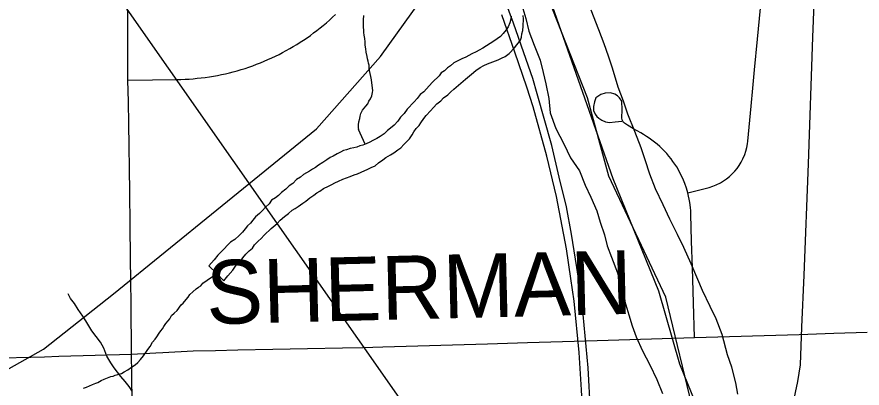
# Model space of a CAD drawing. Extents: x -6.1 to 38, y -7.7 to 22.
# Drawn here: x 4.199 to 4.953, y 17.079 to 17.41 of the extents above; entities that cross this region are included whole.
import ezdxf

# ---------------------------------------------------------------- set-up
doc = ezdxf.new("R2010")
doc.units = 0
for name, color, linetype in [('GM_X_Corporation', 7, 'Continuous'), ('GM_X_County_Road', 7, 'Continuous'), ('GM_X_Major_River', 7, 'Continuous'), ('GM_X_Minor_River', 7, 'Continuous'), ('GM_X_Rail_Line', 7, 'Continuous'), ('GM_X_State_Route', 7, 'Continuous'), ('GM_X_Township_Road', 7, 'Continuous'), ('GM_X_Township_Road_Text', 7, 'Continuous'), ('SH_Text', 7, 'Continuous')]:
    doc.layers.add(name, color=color, linetype=linetype)

msp = doc.modelspace()

# ---------------------------------------------------------------- linework, layer by layer
at = {"layer": 'GM_X_Corporation'}
for points in [[(4.78909, 16.45229), (4.83333, 16.6969), (4.8485, 16.80869), (4.84852, 16.86549), (4.82148, 16.98857), (4.80797, 17.05755), (4.79039, 17.10084), (4.77146, 17.16576), (4.7309, 17.26585), (4.64031, 17.52419)], [(4.78909, 16.45229), (4.83333, 16.6969), (4.8485, 16.80869), (4.84852, 16.86549), (4.82148, 16.98857), (4.80797, 17.05755), (4.79039, 17.10084), (4.77146, 17.16576), (4.7309, 17.26585), (4.64031, 17.52419)], [(4.79218, 16.42728), (4.80873, 16.54217), (4.81265, 16.56116), (4.82853, 16.688), (4.83806, 16.82118), (4.82856, 16.93533), (4.80321, 17.05583), (4.77785, 17.16048), (4.72713, 17.2683), (4.70812, 17.33806), (4.67325, 17.42685)]]:
    msp.add_lwpolyline(points, dxfattribs=at)
at = {"layer": 'GM_X_County_Road'}
for points in [[(4.89028, 17.06011), (4.89554, 17.08535), (4.89792, 17.10008), (4.89925, 17.13375), (4.90132, 17.17999), (4.90503, 17.27928), (4.90895, 17.39239), (4.91279, 17.48998), (4.9171, 17.61923)], [(4.30194, 17.068), (4.30177, 17.08928), (4.30175, 17.09175), (4.30125, 17.10979), (4.30097, 17.15446), (4.30077, 17.17486), (4.30056, 17.19526), (4.3002, 17.22476), (4.29983, 17.25426), (4.29963, 17.27505), (4.29928, 17.29504), (4.29893, 17.31504), (4.29857, 17.33451), (4.2982, 17.35397), (4.29791, 17.40721), (4.29771, 17.42365)]]:
    msp.add_lwpolyline(points, dxfattribs=at)
at = {"layer": 'GM_X_Major_River'}
for p, q in [((4.37025, 17.18857), (4.37728, 17.18147)), ((4.37728, 17.18147), (4.38359, 17.17509))]:
    msp.add_line(p, q, dxfattribs=at)
for points in [[(4.64846, 17.42364), (4.65309, 17.40889), (4.65581, 17.39753), (4.66043, 17.38504), (4.66582, 17.37181), (4.66854, 17.36083), (4.67087, 17.3506), (4.67361, 17.33773), (4.67482, 17.32485), (4.67983, 17.31085), (4.68673, 17.29724), (4.69286, 17.28477), (4.70088, 17.27307), (4.70589, 17.26021), (4.71087, 17.24963), (4.71625, 17.23753), (4.71934, 17.22731), (4.7232, 17.21596), (4.72553, 17.20612), (4.72938, 17.19628), (4.73476, 17.18229), (4.73711, 17.17131), (4.74136, 17.15655), (4.74485, 17.14482), (4.74793, 17.13498), (4.7514, 17.12514), (4.75716, 17.11267), (4.76367, 17.1002), (4.76981, 17.08697), (4.77481, 17.07449)], [(4.65074, 17.40204), (4.65086, 17.40849), (4.65054, 17.41154)], [(4.84213, 17.07417), (4.84017, 17.08402), (4.83668, 17.09803), (4.83282, 17.109), (4.82816, 17.12717), (4.82278, 17.14116), (4.81741, 17.15213), (4.81051, 17.16649), (4.80628, 17.17632), (4.80052, 17.19031), (4.79399, 17.20468), (4.78824, 17.21639), (4.78135, 17.23), (4.77559, 17.24285), (4.76869, 17.25722), (4.76368, 17.27008), (4.75944, 17.28294), (4.75597, 17.29353), (4.7502, 17.30828), (4.74404, 17.32379), (4.74018, 17.33514), (4.73519, 17.34762), (4.73016, 17.36465), (4.72668, 17.37524), (4.72283, 17.38622), (4.71821, 17.3987), (4.71128, 17.41648)], [(4.63993, 17.41097), (4.6395, 17.40832), (4.63868, 17.40492), (4.6371, 17.40153), (4.63553, 17.39891), (4.63282, 17.39554), (4.6305, 17.39292), (4.62743, 17.3907), (4.62436, 17.38886), (4.62129, 17.38664), (4.61784, 17.38443), (4.61478, 17.38258), (4.61133, 17.38075), (4.60866, 17.37928), (4.60484, 17.37745), (4.59948, 17.37451), (4.59604, 17.37306), (4.59222, 17.37123), (4.58878, 17.3694), (4.5857, 17.36679), (4.58302, 17.36495), (4.58032, 17.36234), (4.57763, 17.36049), (4.57569, 17.35787), (4.5699, 17.35228), (4.56681, 17.34892), (4.56217, 17.34369), (4.55871, 17.3411), (4.55599, 17.33773), (4.55329, 17.33474), (4.5471, 17.32802), (4.54438, 17.32428), (4.54129, 17.32092), (4.53895, 17.31754), (4.53547, 17.31381), (4.53239, 17.31121), (4.5297, 17.30898), (4.52661, 17.306), (4.52316, 17.30379), (4.5201, 17.30194), (4.51666, 17.30011), (4.51398, 17.29864), (4.51054, 17.29719), (4.50749, 17.2961), (4.50483, 17.2954), (4.50216, 17.2943), (4.4995, 17.29359), (4.49645, 17.29289), (4.49303, 17.29182), (4.49036, 17.29111), (4.48768, 17.28964), (4.48463, 17.28818), (4.48118, 17.28634), (4.47851, 17.28487), (4.47544, 17.28303), (4.47199, 17.28044), (4.46816, 17.27823), (4.46547, 17.276), (4.46279, 17.27453), (4.4601, 17.27268), (4.45742, 17.27121), (4.45475, 17.26974), (4.45205, 17.26751), (4.4486, 17.2653), (4.44513, 17.26195), (4.44206, 17.25973), (4.43897, 17.25675), (4.43513, 17.25378), (4.43243, 17.25117), (4.42974, 17.24894), (4.4263, 17.24711), (4.42396, 17.24374), (4.42087, 17.24076), (4.41817, 17.23777), (4.41547, 17.23516), (4.412, 17.23219), (4.40967, 17.22919), (4.40735, 17.22658), (4.40465, 17.22397), (4.40271, 17.22135), (4.40038, 17.21835), (4.39729, 17.21537), (4.39344, 17.21203), (4.38961, 17.20944), (4.38652, 17.20646), (4.3842, 17.20385), (4.38111, 17.20049), (4.3784, 17.19788), (4.37492, 17.19377), (4.3726, 17.19115), (4.37025, 17.18857)], [(4.38359, 17.17509), (4.38714, 17.17949), (4.39178, 17.18472), (4.39412, 17.1881), (4.39606, 17.19072), (4.39875, 17.19295), (4.4007, 17.19557), (4.40341, 17.19894), (4.40612, 17.20192), (4.40919, 17.20414), (4.41114, 17.20714), (4.41423, 17.21051), (4.41693, 17.21273), (4.41963, 17.21572), (4.42581, 17.22168), (4.43119, 17.22614), (4.4339, 17.22912), (4.43775, 17.23247), (4.44121, 17.23506), (4.44467, 17.23804), (4.44735, 17.23951), (4.45003, 17.24135), (4.45425, 17.24431), (4.45694, 17.24616), (4.4604, 17.24914), (4.46385, 17.25135), (4.46655, 17.25358), (4.46922, 17.25505), (4.47268, 17.25726), (4.47688, 17.25946), (4.47994, 17.26092), (4.48262, 17.26239), (4.48605, 17.26385), (4.48987, 17.26568), (4.49292, 17.26676), (4.49636, 17.26822), (4.49979, 17.26967), (4.50283, 17.27037), (4.50627, 17.27183), (4.512, 17.27476), (4.51506, 17.27622), (4.51849, 17.27768), (4.52157, 17.28028), (4.52541, 17.28286), (4.5281, 17.28509), (4.53231, 17.28729), (4.53537, 17.28913), (4.53883, 17.29173), (4.54151, 17.29358), (4.54422, 17.29656), (4.54692, 17.29917), (4.54925, 17.30179), (4.55158, 17.30516), (4.55315, 17.30779), (4.5551, 17.31079), (4.5578, 17.3134), (4.55936, 17.31603), (4.56208, 17.31977), (4.56403, 17.3224), (4.56789, 17.3265), (4.5706, 17.32949), (4.57369, 17.33285), (4.57715, 17.33544), (4.57947, 17.33806), (4.58331, 17.34102), (4.58601, 17.34363), (4.58871, 17.34586), (4.59294, 17.34958), (4.5991, 17.35478), (4.60449, 17.35923), (4.60833, 17.36258), (4.61217, 17.36517), (4.61561, 17.367), (4.61867, 17.36846), (4.6282, 17.37208), (4.63126, 17.37354), (4.63469, 17.375), (4.63815, 17.37759), (4.6428, 17.38283), (4.64822, 17.38956), (4.64903, 17.3922), (4.64947, 17.39523), (4.65028, 17.39825), (4.65074, 17.40204)], [(4.33564, 17.14119), (4.3371, 17.14426), (4.33934, 17.1462), (4.34196, 17.14853), (4.34567, 17.15354), (4.34754, 17.15509), (4.35014, 17.15856), (4.352, 17.1605), (4.35348, 17.1628), (4.3561, 17.16513), (4.35909, 17.16785), (4.36096, 17.1694), (4.36322, 17.17058), (4.36507, 17.1729), (4.37728, 17.18147)], [(4.2585, 17.07935), (4.26115, 17.08016), (4.26379, 17.08134), (4.26642, 17.08253), (4.26944, 17.08373), (4.27132, 17.08452), (4.27434, 17.0861), (4.27697, 17.08729), (4.27999, 17.08848), (4.28301, 17.08968), (4.2849, 17.09009), (4.28678, 17.09088), (4.28905, 17.09169), (4.29245, 17.09251), (4.2947, 17.09407), (4.29809, 17.09565), (4.30147, 17.09799), (4.30447, 17.10033), (4.30709, 17.10228), (4.30932, 17.10498), (4.31192, 17.10807), (4.31415, 17.11115), (4.316, 17.11384), (4.31785, 17.11654), (4.32006, 17.12038), (4.32229, 17.12308), (4.32377, 17.12501), (4.32599, 17.12847), (4.32747, 17.1304), (4.32896, 17.13233), (4.33006, 17.13425), (4.33191, 17.13694), (4.33415, 17.13926), (4.33564, 17.14119)]]:
    msp.add_lwpolyline(points, dxfattribs=at)
at = {"layer": 'GM_X_Minor_River'}
for points in [[(4.50977, 17.29691), (4.5039, 17.31), (4.50391, 17.30962), (4.50387, 17.3119), (4.50382, 17.31418), (4.50416, 17.31685), (4.50486, 17.3199), (4.50521, 17.32181), (4.50593, 17.3241), (4.50739, 17.32717), (4.51037, 17.33065), (4.51222, 17.33296), (4.51294, 17.33526), (4.51443, 17.33719), (4.51552, 17.33987), (4.51622, 17.34292), (4.51657, 17.34483), (4.51569, 17.35166), (4.51526, 17.35431), (4.51482, 17.35734), (4.51402, 17.35999), (4.51359, 17.36265), (4.51317, 17.36492), (4.51313, 17.3672), (4.51272, 17.36909), (4.5123, 17.37099), (4.51189, 17.37288), (4.51147, 17.37516), (4.51064, 17.37894), (4.51021, 17.38198), (4.50977, 17.38501), (4.50972, 17.38805), (4.50928, 17.39109), (4.50885, 17.39412), (4.50843, 17.3964), (4.50839, 17.39867), (4.50834, 17.40133), (4.50829, 17.40438), (4.50822, 17.4078), (4.50854, 17.41161)], [(4.30183, 17.07659), (4.29917, 17.08075), (4.29575, 17.08528), (4.29195, 17.08981), (4.28587, 17.09737), (4.28282, 17.1019), (4.27939, 17.10795), (4.27671, 17.11514), (4.27366, 17.12043), (4.26606, 17.13064), (4.26073, 17.13933), (4.25806, 17.14349), (4.25388, 17.14953), (4.25045, 17.15482), (4.24703, 17.15936), (4.24474, 17.16352)]]:
    msp.add_lwpolyline(points, dxfattribs=at)
at = {"layer": 'GM_X_Rail_Line'}
msp.add_lwpolyline([(4.164, 17.08105), (4.22288, 17.11422), (4.28514, 17.16362), (4.3773, 17.2385), (4.46626, 17.31066), (4.52352, 17.37506), (4.57967, 17.45347), (4.643, 17.54537), (5.03778, 18.11028), (5.18813, 18.32179), (5.2285, 18.37664), (5.2671, 18.40903), (5.31379, 18.44323), (5.44065, 18.5342), (5.77322, 18.77518), (5.85708, 18.83753), (5.92575, 18.89871), (5.97472, 18.97128), (6.00159, 19.04095), (6.01392, 19.09362), (6.04108, 19.2873)], dxfattribs=at)
at = {"layer": 'GM_X_State_Route'}
for points in [[(4.73191, 16.43722), (4.73473, 16.47674), (4.73604, 16.51756), (4.73647, 16.54406), (4.73495, 16.5825), (4.73365, 16.60985), (4.7308, 16.66851), (4.72201, 16.83981), (4.71299, 17.00788), (4.71063, 17.05893), (4.70846, 17.09758), (4.70411, 17.14492), (4.70107, 17.16946), (4.69847, 17.18705), (4.69369, 17.2168), (4.68935, 17.24091), (4.68283, 17.26739), (4.67632, 17.29584), (4.66309, 17.34173), (4.65916, 17.35556), (4.6533, 17.37228), (4.64201, 17.40485), (4.62572, 17.44915)], [(4.7267, 16.45524), (4.72952, 16.51539), (4.72952, 16.54971), (4.72779, 16.59376), (4.72605, 16.63222), (4.72323, 16.68586), (4.71954, 16.761), (4.71476, 16.84025), (4.7128, 16.88108), (4.70889, 16.96099), (4.70651, 17.00442), (4.7052, 17.02896), (4.7026, 17.07782), (4.70064, 17.11126), (4.69608, 17.15708), (4.69304, 17.17728), (4.68935, 17.20356), (4.68023, 17.25024), (4.67176, 17.28607), (4.65938, 17.33015), (4.65395, 17.34774), (4.64331, 17.37901), (4.63167, 17.41214)]]:
    msp.add_lwpolyline(points, dxfattribs=at)
at = {"layer": 'GM_X_Township_Road'}
for points in [[(4.2982, 17.35397), (4.32, 17.35427), (4.3418, 17.35456), (4.3454, 17.35464), (4.34904, 17.35478), (4.35269, 17.35499), (4.3563, 17.35527), (4.35994, 17.35559), (4.36355, 17.35599), (4.36714, 17.35645), (4.37075, 17.35697), (4.37435, 17.35756), (4.37795, 17.35821), (4.3815, 17.35893), (4.38506, 17.35969), (4.38861, 17.36053), (4.39212, 17.36143), (4.39562, 17.36239), (4.39913, 17.36341), (4.40259, 17.36449), (4.40605, 17.36563), (4.40951, 17.36682), (4.41292, 17.36808), (4.41629, 17.36941), (4.41965, 17.37079), (4.42302, 17.37223), (4.42633, 17.37372), (4.4296, 17.37527), (4.43287, 17.37688), (4.4361, 17.37855), (4.43932, 17.38028), (4.44249, 17.38205), (4.44562, 17.38389), (4.44875, 17.38578), (4.45183, 17.38772), (4.45486, 17.38972), (4.45785, 17.39176), (4.46083, 17.39387), (4.46377, 17.39601), (4.46666, 17.39822), (4.46951, 17.40048), (4.47235, 17.40278), (4.4751, 17.40513), (4.47785, 17.40752), (4.48056, 17.40997), (4.48321, 17.41247)], [(4.79741, 17.2534), (4.81655, 17.25841), (4.81968, 17.25941), (4.82276, 17.26062), (4.8265, 17.26245), (4.82934, 17.26413), (4.83205, 17.26601), (4.83465, 17.26808), (4.83707, 17.27032), (4.83935, 17.27272), (4.84143, 17.27528), (4.84333, 17.27798), (4.84508, 17.2808), (4.8466, 17.28374), (4.84822, 17.28755), (4.84926, 17.29069), (4.85007, 17.29389), (4.85063, 17.29714), (4.85097, 17.29972), (4.85389, 17.33065), (4.85542, 17.34693), (4.85696, 17.36322), (4.85954, 17.39065), (4.86213, 17.41809)], [(4.80345, 17.12454), (4.80252, 17.15559), (4.80158, 17.18665), (4.80087, 17.21054), (4.80015, 17.23442), (4.8, 17.23739), (4.79977, 17.24035), (4.7992, 17.24478), (4.79868, 17.24772), (4.79806, 17.25063), (4.79741, 17.2534), (4.79618, 17.25769), (4.79471, 17.26191), (4.79362, 17.26467), (4.79244, 17.2674), (4.79045, 17.27141), (4.78903, 17.27402), (4.78751, 17.27659), (4.7859, 17.27909), (4.7842, 17.28154), (4.78245, 17.28392), (4.78055, 17.28626), (4.77861, 17.28851), (4.77662, 17.2907), (4.77454, 17.29282), (4.77236, 17.29486), (4.77013, 17.29683), (4.76782, 17.29871), (4.76545, 17.30053), (4.76303, 17.30224), (4.76052, 17.30388), (4.75801, 17.30543), (4.75541, 17.30689), (4.74905, 17.31058), (4.74358, 17.31393), (4.74009, 17.31636), (4.73936, 17.31742), (4.73893, 17.31872), (4.73858, 17.32045), (4.73903, 17.3276), (4.73857, 17.33534), (4.7366, 17.33823), (4.73462, 17.34005), (4.73249, 17.34158), (4.72839, 17.34264), (4.72384, 17.34248), (4.71973, 17.34112), (4.71533, 17.33808), (4.71411, 17.33474), (4.7132, 17.33049), (4.71335, 17.32699), (4.71488, 17.32365), (4.71624, 17.32167), (4.71821, 17.32), (4.7208, 17.31833), (4.72404, 17.31694), (4.72748, 17.31636), (4.7328, 17.31666), (4.73857, 17.31727)], [(4.65448, 17.12005), (4.68554, 17.12098), (4.7166, 17.12192), (4.7456, 17.12279), (4.7746, 17.12366), (4.80345, 17.12454), (4.83451, 17.12547), (4.86556, 17.1264), (4.89662, 17.12734), (4.92768, 17.12827), (4.95737, 17.12917)], [(4.32914, 17.11119), (4.35642, 17.11258), (4.37634, 17.11307), (4.39626, 17.11358), (4.42732, 17.11419), (4.45839, 17.1148), (4.48945, 17.1154), (4.50752, 17.11575), (4.52559, 17.11611), (4.55664, 17.11706), (4.5877, 17.11801), (4.61876, 17.11896), (4.63662, 17.11951), (4.65448, 17.12005)], [(4.18565, 17.10631), (4.21169, 17.10701), (4.22386, 17.1074), (4.2364, 17.10793), (4.30125, 17.10979)], [(4.30125, 17.10979), (4.32308, 17.11089), (4.32914, 17.11119)]]:
    msp.add_lwpolyline(points, dxfattribs=at)
at = {"layer": 'SH_Text'}
msp.add_lwpolyline([(4.05377, 17.76448), (4.89626, 16.56236), (4.05377, 17.09999)], close=True, dxfattribs=at)

# ---------------------------------------------------------------- texts
at = {"layer": 'GM_X_Township_Road_Text'}
msp.add_text('SHERMAN', height=0.056818, rotation=1.40861, dxfattribs=at).set_placement((4.36856, 17.13632))

doc.saveas('drawing.dxf')
